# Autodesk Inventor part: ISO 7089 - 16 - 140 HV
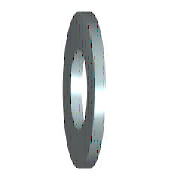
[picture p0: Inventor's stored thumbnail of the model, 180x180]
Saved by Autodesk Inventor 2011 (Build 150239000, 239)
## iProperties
Created: 2009-02
Part Number: ISO 7089 - 16 - 140 HV
Material: Stainless Steel
Description: Plain washers - Normal series - Product grade A
Document SubType Name: Modeling
Standard: ISO 7089
Designer: V.de Jong
Standard Revision: Second edition 2000-06-01
Standards Organization: ISO
Language: en-US
Size Designation: 16 - 140 HV
Categories: <MemberInstance><Categories><Category DisplayName="Fasteners" InternalName="e4da775c-781d-43d5-af7c-5136215cf5a6" Mnemonic="FSTN"><Category DisplayName="Washers
Density: 8.08 g/cm^3
Mass: 11.6322 g
Surface Area: 14.0272 cm^2
Volume: 1.43963 cm^3
IsCustomPart: 0
Author: V.de Jong
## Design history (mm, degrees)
body "Solid1"
sketch "Sketch"
  geometry: C1 r 15 at (0, 0); C2 r 8.5 at (0, 0); 1 further point
  constraints: 2 centre point, 2 coincident
  dimensions: "d0" = 17 diameter of C2 (= SD1); "d1" = 30 diameter of C1 (= SD2)
extrude "Body" new body sketch "Sketch" distance "d2" = 3 (= SD); taper "d3" = 0 deg
workaxis "Work Axis1"
workplane "Work Plane1"
other parameters: "SD1" = 17 [user parameter; used in 1 equation term], "SD2" = 30 [user parameter; used in 1 equation term], "SD" = 3 [user parameter; used in 1 equation term], "d4" = 0, "d5" = 0, "d6" = 0, "d7" = 0, "NND" = 16 [user parameter]
